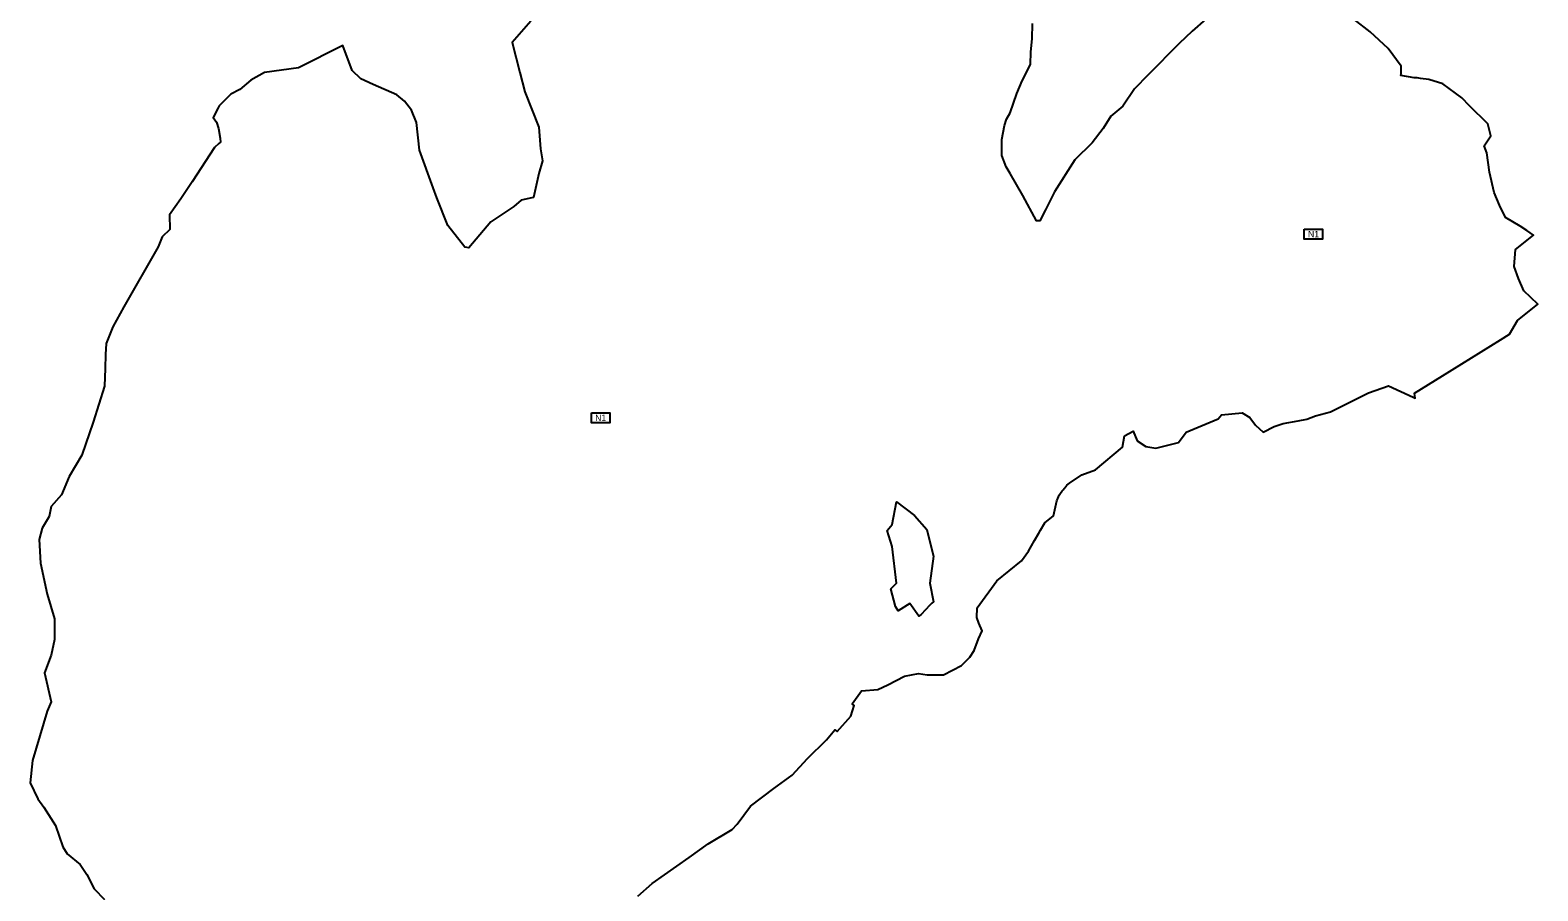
# Model space of a CAD drawing. Extents: x -547623 to -530360, y -1095798 to -1086523.
# Drawn here: x -544695 to -542346, y -1088939 to -1087598 of the extents above; entities that cross this region are included whole.
import ezdxf

# ---------------------------------------------------------------- set-up
doc = ezdxf.new("R2010")
doc.units = 0
for name, color, linetype in [('Vrstva 27', 7, 'Continuous'), ('Vrstva 36', 7, 'Continuous'), ('Vrstva 73', 7, 'Continuous')]:
    doc.layers.add(name, color=color, linetype=linetype)

msp = doc.modelspace()

# ---------------------------------------------------------------- linework, layer by layer
at = {"layer": 'Vrstva 27'}
for points in [[(-543915.2, -1087584), (-543944.4, -1087616.9), (-543932.1, -1087663.6), (-543924.3, -1087694), (-543902.6, -1087748.9), (-543900.1, -1087783), (-543897.2, -1087801.7), (-543902.6, -1087821.2), (-543910.9, -1087858.5), (-543913.5, -1087859.1), (-543930.1, -1087862.6), (-543941.4, -1087872.8), (-543977.2, -1087896.4), (-544011.8, -1087937), (-544017.7, -1087936), (-544044.6, -1087902.4), (-544061.6, -1087859.3), (-544067.2, -1087843.8), (-544088.6, -1087784.8), (-544093.4, -1087741.8), (-544100.8, -1087722.7), (-544112, -1087708.5), (-544124.1, -1087698.5), (-544160.8, -1087682.3)], [(-543748.4, -1088947.7), (-543726.2, -1088927.7), (-543668.3, -1088887.2), (-543638.7, -1088866), (-543601.7, -1088843.9), (-543593.5, -1088835.6), (-543572.8, -1088807.6), (-543536.8, -1088780), (-543508.1, -1088759.1), (-543484, -1088733), (-543454.7, -1088704), (-543441.8, -1088688.3), (-543438, -1088690.9), (-543416.5, -1088667.2), (-543411.4, -1088650.5), (-543414.6, -1088647.7), (-543399.8, -1088627.7), (-543374.8, -1088625.5), (-543359.1, -1088618.2), (-543333.1, -1088604.8), (-543311.1, -1088600.6), (-543297.5, -1088602.6), (-543272.1, -1088602.6), (-543244.4, -1088588), (-543231.4, -1088575.3), (-543224.6, -1088564.9), (-543217.7, -1088546.6), (-543212.3, -1088533.9), (-543217.5, -1088521.9), (-543220.3, -1088513.3), (-543219.6, -1088498.4), (-543189.2, -1088456), (-543150.7, -1088424.8), (-543140, -1088409.8), (-543130.7, -1088393.5), (-543123.8, -1088381.8), (-543121.1, -1088377.2), (-543114.4, -1088365.8), (-543101, -1088354.8), (-543095.8, -1088331.4), (-543093.3, -1088325.1), (-543092.7, -1088323.6), (-543092.2, -1088322.4), (-543091.3, -1088321.2), (-543089.8, -1088319.3), (-543087.2, -1088315.9), (-543085.8, -1088314.1), (-543084.3, -1088312.2), (-543083.5, -1088311.2), (-543080.1, -1088306.8), (-543076, -1088303.9), (-543056.7, -1088290.7), (-543035.4, -1088283.4), (-542993.3, -1088247.8), (-542990.3, -1088230), (-542977, -1088222.9), (-542970.7, -1088237.8), (-542957.2, -1088246.8), (-542941.3, -1088249.5), (-542906.1, -1088240.5), (-542894.4, -1088224.2), (-542844.6, -1088203.7), (-542839.3, -1088197.4), (-542806.8, -1088194.4), (-542795.1, -1088201.7), (-542786.1, -1088213.7), (-542774.2, -1088224.2), (-542757.3, -1088215.6), (-542743.2, -1088210.9), (-542719.6, -1088206.9), (-542706.2, -1088204.3), (-542692.8, -1088198.9), (-542669.6, -1088192.9), (-542610.2, -1088163.3), (-542579.1, -1088152.4), (-542540.9, -1088169.8), (-542537.3, -1088171.4), (-542538, -1088167.6), (-542538.6, -1088163.8), (-542495.1, -1088136.6), (-542404.8, -1088080.4), (-542390.8, -1088071.8), (-542378.3, -1088050.6), (-542346.4, -1088025.1), (-542368.5, -1088004.3), (-542376.5, -1087984.8), (-542383.2, -1087966.3), (-542381.1, -1087939.9), (-542353.4, -1087917.3), (-542363.4, -1087909.9), (-542374.1, -1087903.1), (-542396.6, -1087889.7), (-542406.3, -1087870.4), (-542414.7, -1087851.1), (-542421.9, -1087819.2), (-542425.9, -1087788.9), (-542430.1, -1087778.4), (-542419.6, -1087762.3), (-542424.1, -1087743.8), (-542452.9, -1087715.7), (-542464.8, -1087703.5), (-542494.4, -1087681.3), (-542516.1, -1087674.6), (-542529, -1087673.1), (-542534.4, -1087672.4), (-542539, -1087671.9), (-542559.7, -1087668.3), (-542559.6, -1087665.6), (-542559.5, -1087659.6), (-542559.3, -1087653.8), (-542579.6, -1087626.6), (-542607.4, -1087600.4), (-542633.1, -1087580.6)], [(-542863.8, -1087580.8), (-542884.8, -1087599.6), (-542905.4, -1087618.5), (-542953.6, -1087667.4), (-542974.9, -1087689.1), (-542992.8, -1087716.1), (-543011.8, -1087731.9), (-543023.8, -1087751.3), (-543040.9, -1087773.7), (-543067.9, -1087800), (-543099.2, -1087849.9), (-543113.2, -1087878.1), (-543122.2, -1087895.1), (-543127.3, -1087894.8), (-543148.5, -1087855.4), (-543168.6, -1087821.2), (-543174.6, -1087810.8), (-543181.6, -1087793.1), (-543181.6, -1087768.4), (-543177.1, -1087746.2), (-543174.2, -1087736.6), (-543168.6, -1087726.6), (-543157.9, -1087696.8), (-543149.9, -1087676.7), (-543136.8, -1087651.4), (-543136.1, -1087631.8), (-543134.3, -1087611.4), (-543133.6, -1087587.7)], [(-544160.8, -1087682.3), (-544179.8, -1087673.9), (-544193.2, -1087660.7), (-544208.2, -1087622), (-544276.9, -1087656.4), (-544329.8, -1087663.6), (-544351.3, -1087676), (-544368.6, -1087690.3), (-544382.3, -1087697.4), (-544400.6, -1087715.7), (-544402.3, -1087719), (-544410, -1087734.1), (-544404.6, -1087741.2), (-544401.5, -1087751.2), (-544399, -1087766.4), (-544398.5, -1087772.5)], [(-544398.5, -1087772.5), (-544401.4, -1087774.4), (-544408, -1087780.6), (-544442.9, -1087834), (-544460.4, -1087860.8), (-544478, -1087885.6), (-544477.3, -1087908.6), (-544489.2, -1087919.8), (-544495.9, -1087935.5), (-544549, -1088029.3), (-544566.3, -1088060.3), (-544576.5, -1088086.1), (-544577.7, -1088103.5), (-544578.3, -1088125.3), (-544579, -1088152.5), (-544597.1, -1088209.1), (-544614.7, -1088260.3), (-544634.3, -1088293.5), (-544646.1, -1088321.9), (-544662.2, -1088340.5), (-544665.2, -1088356), (-544676.3, -1088374.3), (-544681.2, -1088391.8), (-544679, -1088428.8), (-544668.7, -1088476.7), (-544657.1, -1088515.2), (-544657, -1088547.6), (-544662.3, -1088571.8), (-544672.7, -1088599.3), (-544662.4, -1088644.8), (-544668.7, -1088659.5), (-544691.3, -1088736.1), (-544695.1, -1088771.2), (-544683, -1088796.1), (-544673.6, -1088809.1), (-544655.6, -1088837.5), (-544643.9, -1088870.8), (-544637.3, -1088881.5), (-544617.2, -1088898.4), (-544606.8, -1088914.1), (-544595.4, -1088936.4), (-544579.5, -1088952.6)], [(-543345.5, -1088332.9), (-543317.4, -1088354.3), (-543298, -1088376.1), (-543293.2, -1088397.4), (-543288.1, -1088417.7), (-543293.4, -1088459.7), (-543288.1, -1088488.7), (-543290.6, -1088491.2), (-543293.4, -1088494.1), (-543307, -1088508.4), (-543310.9, -1088511.3), (-543324.5, -1088491.5), (-543343.1, -1088502.8), (-543347.3, -1088496), (-543354.5, -1088468.8), (-543345.6, -1088460), (-543352.4, -1088402.4), (-543360, -1088377.9), (-543352.5, -1088368.3), (-543345.5, -1088332.9)]]:
    msp.add_lwpolyline(points, dxfattribs=at)
at = {"layer": 'Vrstva 36'}
for points in [[(-542710.3, -1087908), (-542681.7, -1087908), (-542681.7, -1087923.5), (-542710.3, -1087923.5)], [(-543820.8, -1088194.3), (-543792.2, -1088194.3), (-543792.2, -1088209.8), (-543820.8, -1088209.8)]]:
    msp.add_lwpolyline(points, close=True, dxfattribs=at)
at = {"layer": 'Vrstva 73'}
for points in [[(-543915.2, -1087584), (-543944.4, -1087616.9), (-543932.1, -1087663.6), (-543924.3, -1087694), (-543902.6, -1087748.9), (-543900.1, -1087783), (-543897.2, -1087801.7), (-543902.6, -1087821.2), (-543910.9, -1087858.5), (-543913.5, -1087859.1), (-543930.1, -1087862.6), (-543941.4, -1087872.8), (-543977.2, -1087896.4), (-544011.8, -1087937), (-544017.7, -1087936), (-544044.6, -1087902.4), (-544061.6, -1087859.3), (-544067.2, -1087843.8), (-544088.6, -1087784.8), (-544093.4, -1087741.8), (-544100.8, -1087722.7), (-544112, -1087708.5), (-544124.1, -1087698.5), (-544160.8, -1087682.3), (-544179.8, -1087673.9), (-544193.2, -1087660.7), (-544208.2, -1087622), (-544276.9, -1087656.4), (-544329.8, -1087663.6), (-544351.3, -1087676), (-544368.6, -1087690.3), (-544382.3, -1087697.4), (-544400.6, -1087715.7), (-544402.3, -1087719), (-544410, -1087734.1), (-544404.6, -1087741.2), (-544401.5, -1087751.2), (-544399, -1087766.4), (-544398.5, -1087772.5), (-544401.4, -1087774.4), (-544408, -1087780.6), (-544442.9, -1087834), (-544460.4, -1087860.8), (-544478, -1087885.6), (-544477.3, -1087908.6), (-544489.2, -1087919.8), (-544495.9, -1087935.5), (-544549, -1088029.3), (-544566.3, -1088060.3), (-544576.5, -1088086.1), (-544577.7, -1088103.5), (-544578.3, -1088125.3), (-544579, -1088152.5), (-544597.1, -1088209.1), (-544614.7, -1088260.3), (-544634.3, -1088293.5), (-544646.1, -1088321.9), (-544662.2, -1088340.5), (-544665.2, -1088356), (-544676.3, -1088374.3), (-544681.2, -1088391.8), (-544679, -1088428.8), (-544668.7, -1088476.7), (-544657.1, -1088515.2), (-544657, -1088547.6), (-544662.3, -1088571.8), (-544672.7, -1088599.3), (-544662.4, -1088644.8), (-544668.7, -1088659.5), (-544691.3, -1088736.1), (-544695.1, -1088771.2), (-544683, -1088796.1), (-544673.6, -1088809.1), (-544655.6, -1088837.5), (-544643.9, -1088870.8), (-544637.3, -1088881.5), (-544617.2, -1088898.4), (-544606.8, -1088914.1), (-544595.4, -1088936.4), (-544579.5, -1088952.6)], [(-543748.4, -1088947.7), (-543726.2, -1088927.7), (-543668.3, -1088887.2), (-543638.7, -1088866), (-543601.7, -1088843.9), (-543593.5, -1088835.6), (-543572.8, -1088807.6), (-543536.8, -1088780), (-543508.1, -1088759.1), (-543484, -1088733), (-543454.7, -1088704), (-543441.8, -1088688.3), (-543438, -1088690.9), (-543416.5, -1088667.2), (-543411.4, -1088650.5), (-543414.6, -1088647.7), (-543399.8, -1088627.7), (-543374.8, -1088625.5), (-543359.1, -1088618.2), (-543333.1, -1088604.8), (-543311.1, -1088600.6), (-543297.5, -1088602.6), (-543272.1, -1088602.6), (-543244.4, -1088588), (-543231.4, -1088575.3), (-543224.6, -1088564.9), (-543217.7, -1088546.6), (-543212.3, -1088533.9), (-543217.5, -1088521.9), (-543220.3, -1088513.3), (-543219.6, -1088498.4), (-543189.2, -1088456), (-543150.7, -1088424.8), (-543140, -1088409.8), (-543130.7, -1088393.5), (-543123.8, -1088381.8), (-543121.1, -1088377.2), (-543114.4, -1088365.8), (-543101, -1088354.8), (-543095.8, -1088331.4), (-543093.3, -1088325.1), (-543092.7, -1088323.6), (-543092.2, -1088322.4), (-543091.3, -1088321.2), (-543089.8, -1088319.3), (-543087.2, -1088315.9), (-543085.8, -1088314.1), (-543084.3, -1088312.2), (-543083.5, -1088311.2), (-543080.1, -1088306.8), (-543076, -1088303.9), (-543056.7, -1088290.7), (-543035.4, -1088283.4), (-542993.3, -1088247.8), (-542990.3, -1088230), (-542977, -1088222.9), (-542970.7, -1088237.8), (-542957.2, -1088246.8), (-542941.3, -1088249.5), (-542906.1, -1088240.5), (-542894.4, -1088224.2), (-542844.6, -1088203.7), (-542839.3, -1088197.4), (-542806.8, -1088194.4), (-542795.1, -1088201.7), (-542786.1, -1088213.7), (-542774.2, -1088224.2), (-542757.3, -1088215.6), (-542743.2, -1088210.9), (-542719.6, -1088206.9), (-542706.2, -1088204.3), (-542692.8, -1088198.9), (-542669.6, -1088192.9), (-542610.2, -1088163.3), (-542579.1, -1088152.4), (-542540.9, -1088169.8), (-542537.3, -1088171.4), (-542538, -1088167.6), (-542538.6, -1088163.8), (-542495.1, -1088136.6), (-542404.8, -1088080.4), (-542390.8, -1088071.8), (-542378.3, -1088050.6), (-542346.4, -1088025.1), (-542368.5, -1088004.3), (-542376.5, -1087984.8), (-542383.2, -1087966.3), (-542381.1, -1087939.9), (-542353.4, -1087917.3), (-542363.4, -1087909.9), (-542374.1, -1087903.1), (-542396.6, -1087889.7), (-542406.3, -1087870.4), (-542414.7, -1087851.1), (-542421.9, -1087819.2), (-542425.9, -1087788.9), (-542430.1, -1087778.4), (-542419.6, -1087762.3), (-542424.1, -1087743.8), (-542452.9, -1087715.7), (-542464.8, -1087703.5), (-542494.4, -1087681.3), (-542516.1, -1087674.6), (-542529, -1087673.1), (-542534.4, -1087672.4), (-542539, -1087671.9), (-542559.7, -1087668.3), (-542559.6, -1087665.6), (-542559.5, -1087659.6), (-542559.3, -1087653.8), (-542579.6, -1087626.6), (-542607.4, -1087600.4), (-542633.1, -1087580.6)], [(-542863.8, -1087580.8), (-542884.8, -1087599.6), (-542905.4, -1087618.5), (-542953.6, -1087667.4), (-542974.9, -1087689.1), (-542992.8, -1087716.1), (-543011.8, -1087731.9), (-543023.8, -1087751.3), (-543040.9, -1087773.7), (-543067.9, -1087800), (-543099.2, -1087849.9), (-543113.2, -1087878.1), (-543122.2, -1087895.1), (-543127.3, -1087894.8), (-543148.5, -1087855.4), (-543168.6, -1087821.2), (-543174.6, -1087810.8), (-543181.6, -1087793.1), (-543181.6, -1087768.4), (-543177.1, -1087746.2), (-543174.2, -1087736.6), (-543168.6, -1087726.6), (-543157.9, -1087696.8), (-543149.9, -1087676.7), (-543136.8, -1087651.4), (-543136.1, -1087631.8), (-543134.3, -1087611.4), (-543133.6, -1087587.7)], [(-543352.5, -1088368.3), (-543345.5, -1088332.9), (-543317.4, -1088354.3), (-543298, -1088376.1), (-543293.2, -1088397.4), (-543288.1, -1088417.7), (-543293.4, -1088459.7), (-543288.1, -1088488.7), (-543290.6, -1088491.2), (-543293.4, -1088494.1), (-543307, -1088508.4), (-543310.9, -1088511.3), (-543324.5, -1088491.5), (-543343.1, -1088502.8), (-543347.3, -1088496), (-543354.5, -1088468.8), (-543345.6, -1088460), (-543352.4, -1088402.4), (-543360, -1088377.9), (-543352.5, -1088368.3)]]:
    msp.add_lwpolyline(points, dxfattribs=at)

# ---------------------------------------------------------------- texts
at = {"layer": 'Vrstva 36'}
for p in [(-542704.4, -1087920.7), (-543814.9, -1088207)]:
    msp.add_text('N1', height=10, dxfattribs=at).set_placement(p)

doc.saveas('drawing.dxf')
